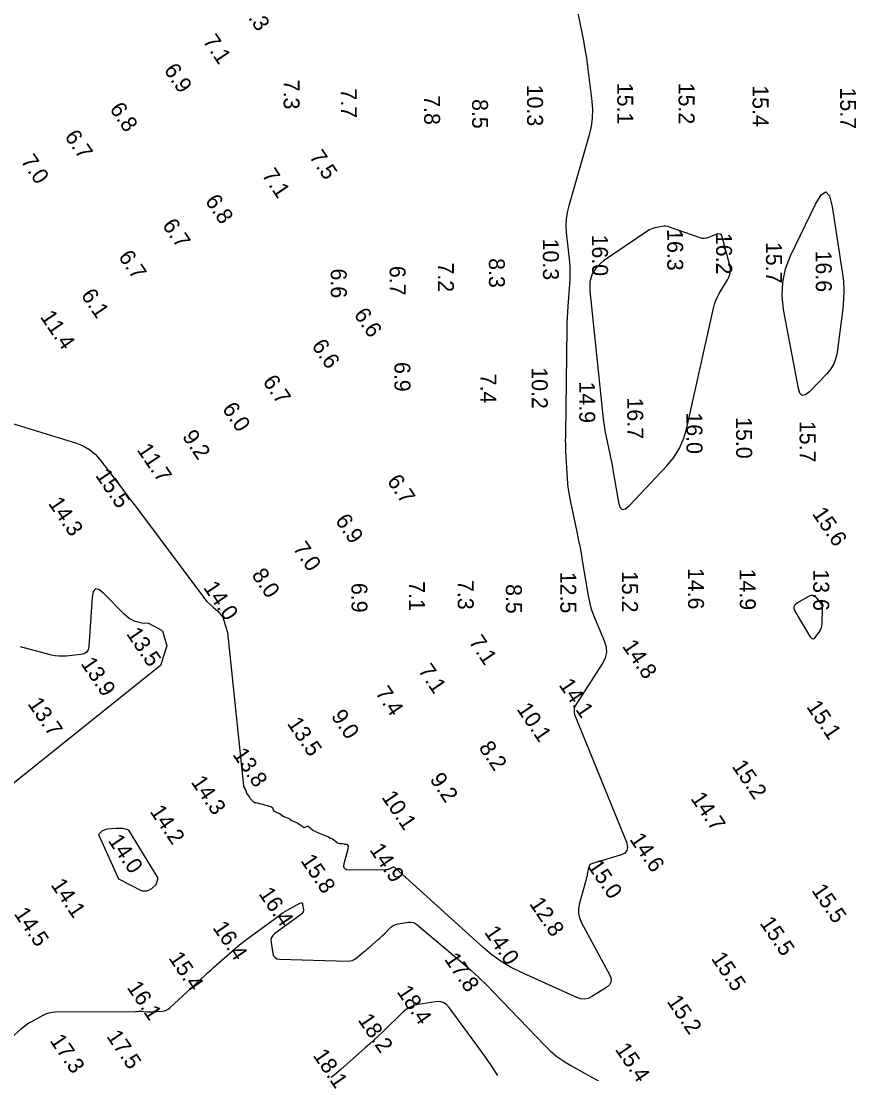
# Model space of a CAD drawing. Extents: x 824616 to 827440, y 158441 to 163197.
# Drawn here: x 826348.7 to 826608.3, y 160568.9 to 160898.9 of the extents above; entities that cross this region are included whole.
import ezdxf

# ---------------------------------------------------------------- set-up
doc = ezdxf.new("R2010")
doc.units = 0
for name, color, linetype in [('V-CHAN-CONT-EL14', 7, 'Continuous'), ('V-CHAN-CONT-EL16', 7, 'Continuous'), ('V-CHAN-CONT-EL18', 7, 'Continuous'), ('V-TOPO-SOUN', 7, 'Continuous')]:
    doc.layers.add(name, color=color, linetype=linetype)

msp = doc.modelspace()

# ---------------------------------------------------------------- linework, layer by layer
at = {"layer": 'V-CHAN-CONT-EL14'}
for points in [[(826521.03, 160912.14), (826524.52, 160895.34), (826525.05, 160892.67), (826525.52, 160889.99), (826525.94, 160887.3), (826526.31, 160884.61), (826527.66, 160873.81), (826527.86, 160871.12), (826527.79, 160868.45), (826527.44, 160865.8), (826526.82, 160863.18), (826520.41, 160840.94), (826519.92, 160838.88), (826519.63, 160836.81), (826519.54, 160834.72), (826519.66, 160832.61), (826520.61, 160823.39), (826520.75, 160821.65), (826520.81, 160819.92), (826520.79, 160818.18), (826520.69, 160816.44), (826520.14, 160809.49), (826520.01, 160807.75), (826519.92, 160806.01), (826519.85, 160804.27), (826519.82, 160802.53), (826519.53, 160777.56), (826519.52, 160776.43), (826519.5, 160775.29), (826519.48, 160774.16), (826519.46, 160773.02), (826519.36, 160768.48), (826519.35, 160767.35), (826519.36, 160766.21), (826519.39, 160765.08), (826519.44, 160763.95), (826519.92, 160755.61), (826520.05, 160753.84), (826520.25, 160752.09), (826520.52, 160750.34), (826520.86, 160748.61), (826522.96, 160738.75), (826523.42, 160736.52), (826523.86, 160734.3), (826524.27, 160732.06), (826524.66, 160729.83), (826526.53, 160718.69), (826526.9, 160716.83), (826527.38, 160714.99), (826527.97, 160713.19), (826528.66, 160711.42), (826531.65, 160704.4), (826532.17, 160702.66), (826532.25, 160700.96), (826531.88, 160699.3), (826531.07, 160697.68), (826522.43, 160684.28), (826522.32, 160684.08), (826522.24, 160683.88), (826522.19, 160683.67), (826522.17, 160683.45), (826522.14, 160682.21), (826522.14, 160682.15), (826522.15, 160682.09), (826522.15, 160682.04), (826522.16, 160681.98), (826522.21, 160681.76), (826522.23, 160681.71), (826522.24, 160681.65), (826522.26, 160681.6), (826522.28, 160681.55), (826538.52, 160641.48), (826538.87, 160640.05), (826538.66, 160638.9), (826537.89, 160638.01), (826536.55, 160637.4), (826527.82, 160634.85), (826527.37, 160634.66), (826527.02, 160634.38), (826526.78, 160634), (826526.63, 160633.54), (826526.25, 160631.49), (826526.15, 160630.98), (826526.04, 160630.47), (826525.92, 160629.97), (826525.79, 160629.47), (826523.74, 160621.93), (826523.49, 160620.52), (826523.51, 160619.15), (826523.8, 160617.8), (826524.36, 160616.48), (826533.27, 160599.8), (826533.69, 160598.67), (826533.65, 160597.65), (826533.18, 160596.76), (826532.26, 160595.98), (826527.68, 160593.11), (826526.52, 160592.55), (826525.34, 160592.31), (826524.14, 160592.39), (826522.92, 160592.79), (826505.57, 160600.65), (826502.35, 160602.27), (826499.28, 160604.12), (826496.36, 160606.2), (826493.59, 160608.51), (826466.03, 160633.43), (826465.82, 160633.58), (826465.6, 160633.65), (826465.37, 160633.64), (826465.13, 160633.56), (826464.14, 160633.08), (826463.89, 160632.98), (826463.63, 160632.9), (826463.37, 160632.86), (826463.1, 160632.84), (826451.66, 160632.71), (826450.71, 160632.84), (826450.12, 160633.24), (826449.89, 160633.91), (826450.01, 160634.86), (826451.3, 160639.44), (826451.43, 160640.23), (826451.23, 160640.61), (826451.11, 160640.71), (826450.9, 160640.75), (826450.76, 160640.77), (826450.64, 160640.8), (826450.46, 160640.82), (826450.31, 160640.83), (826450.14, 160640.84), (826449.88, 160640.85), (826449.36, 160640.95), (826449.11, 160640.96), (826448.76, 160641.01), (826448.49, 160641.08), (826447.97, 160641.24), (826447.75, 160641.43), (826446.38, 160642.44), (826446.12, 160642.54), (826445.7, 160642.69), (826444.86, 160643.21), (826443.64, 160643.71), (826442.86, 160644.02), (826440.25, 160645.18), (826438.69, 160646.51), (826437.53, 160646.04), (826435.55, 160647.41), (826435.35, 160647.44), (826433.23, 160648.45), (826433.13, 160648.68), (826430.96, 160649.61), (826429.62, 160650.46), (826429, 160650.75), (826428.59, 160650.91), (826428.43, 160650.99), (826428.11, 160651.22), (826427.88, 160651.55), (826427.65, 160652.15), (826427.02, 160652.64), (826425.97, 160652.86), (826422.49, 160653.82), (826421.94, 160653.89), (826421.18, 160654.57), (826420.65, 160655.06), (826420.31, 160655.76), (826419.56, 160656.85), (826419.05, 160658.15), (826418.47, 160659.22)], [(826345.7, 160772.89), (826366.09, 160766.58), (826368.24, 160765.73), (826370.19, 160764.59), (826371.93, 160763.15), (826373.47, 160761.42), (826379.2, 160753.91), (826380.63, 160752.03), (826382.06, 160750.15), (826383.48, 160748.26), (826384.9, 160746.37), (826406.89, 160717.02), (826408.96, 160715.13), (826410.51, 160713.83), (826411.95, 160712.07), (826413.43, 160707.22), (826418.47, 160659.22)], [(826393.08, 160707.77), (826388.77, 160710.09), (826386.57, 160710.15), (826384.53, 160710.66), (826382.67, 160711.63), (826380.98, 160713.04), (826374.55, 160719.61), (826373.13, 160720.76), (826372.06, 160720.92), (826371.36, 160720.11), (826371.03, 160718.31), (826369.97, 160702.87), (826369.76, 160701.84), (826369.28, 160701.07), (826368.52, 160700.56), (826367.51, 160700.31), (826362.89, 160699.83), (826361.74, 160699.77), (826360.6, 160699.8), (826359.47, 160699.94), (826358.34, 160700.18), (826348.54, 160702.77)], [(826393.08, 160707.77), (826394.48, 160703.04), (826392.42, 160696.85), (826339.2, 160654.22)], [(826391.68, 160630.25), (826382.52, 160645.24), (826380.71, 160645.8), (826378.6, 160645.76), (826375.62, 160645.6), (826374.12, 160645.02), (826373.01, 160643.91), (826379.24, 160630.04), (826386.58, 160626.26), (826388.26, 160626.22), (826389.71, 160627.01), (826391.13, 160628.24), (826391.68, 160630.25)]]:
    msp.add_lwpolyline(points, dxfattribs=at)
msp.add_lwpolyline([(826596.84, 160718.98), (826597.26, 160718.82), (826597.65, 160718.48), (826599.16, 160716.74), (826599.48, 160716.29), (826599.71, 160715.8), (826599.84, 160715.28), (826599.88, 160714.73), (826599.73, 160709.91), (826599.67, 160709.31), (826599.53, 160708.74), (826599.31, 160708.19), (826599, 160707.68), (826597.6, 160705.67), (826597.25, 160705.29), (826596.92, 160705.18), (826596.59, 160705.32), (826596.27, 160705.71), (826591.38, 160713.91), (826591.06, 160714.68), (826591.06, 160715.36), (826591.39, 160715.96), (826592.03, 160716.48), (826595.91, 160718.76), (826596.39, 160718.96)], close=True, dxfattribs=at)
at = {"layer": 'V-CHAN-CONT-EL16'}
for points in [[(826600.99, 160845.32), (826602.14, 160844.08), (826602.97, 160840.75), (826606.16, 160820.28), (826606.51, 160817.37), (826606.65, 160814.47), (826606.59, 160811.56), (826606.31, 160808.65), (826604.56, 160795.08), (826604.17, 160793.19), (826603.5, 160791.44), (826602.56, 160789.83), (826601.33, 160788.34), (826595.87, 160782.68), (826594.63, 160781.68), (826593.64, 160781.52), (826592.9, 160782.2), (826592.41, 160783.72), (826587.76, 160808.44), (826587.28, 160812.79), (826587.49, 160817.05), (826588.39, 160821.22), (826589.98, 160825.3), (826597.77, 160841.52), (826599.54, 160844.46)], [(826562.92, 160830.7), (826562.26, 160830.75), (826561.6, 160830.92), (826552.05, 160834.3), (826551.48, 160834.47), (826550.91, 160834.55), (826550.33, 160834.56), (826549.74, 160834.48), (826547.38, 160834.04), (826546.8, 160833.9), (826546.24, 160833.7), (826545.71, 160833.45), (826545.2, 160833.14), (826531.33, 160823.68), (826529.2, 160821.83), (826527.77, 160819.65), (826527.04, 160817.16), (826527, 160814.33), (826531.26, 160774.19), (826531.43, 160772.79), (826531.63, 160771.39), (826531.87, 160770), (826532.15, 160768.61), (826533.33, 160763.09), (826533.61, 160761.7), (826533.89, 160760.32), (826534.14, 160758.93), (826534.39, 160757.54), (826535.97, 160748.12), (826536.45, 160746.52), (826537.19, 160745.82), (826538.2, 160745.99), (826539.48, 160747.05), (826551.13, 160759.42), (826553.34, 160762.1), (826555.13, 160764.99), (826556.51, 160768.1), (826557.48, 160771.42), (826565.78, 160808.94), (826566.1, 160810.14), (826566.51, 160811.3), (826567.02, 160812.42), (826567.62, 160813.51), (826570.23, 160817.77), (826570.76, 160818.85), (826571.04, 160819.97), (826571.08, 160821.12), (826570.88, 160822.31), (826568.5, 160831.24), (826568.26, 160831.8), (826567.91, 160832.13), (826567.43, 160832.21), (826566.84, 160832.06), (826564.23, 160830.99), (826563.58, 160830.78)]]:
    msp.add_lwpolyline(points, close=True, dxfattribs=at)
msp.add_lwpolyline([(826345.52, 160580.13), (826348.77, 160583.02), (826349.55, 160583.68), (826350.36, 160584.28), (826351.2, 160584.84), (826352.08, 160585.36), (826355.65, 160587.32), (826356.56, 160587.74), (826357.5, 160588.05), (826358.48, 160588.24), (826359.48, 160588.31), (826384.67, 160588.43), (826384.8, 160588.43), (826384.93, 160588.44), (826385.07, 160588.46), (826385.2, 160588.48), (826385.72, 160588.58), (826385.85, 160588.6), (826385.98, 160588.61), (826386.11, 160588.61), (826386.24, 160588.59), (826388.24, 160588.35), (826388.61, 160588.32), (826388.99, 160588.3), (826389.37, 160588.3), (826389.75, 160588.32), (826393.01, 160588.58), (826393.66, 160588.68), (826394.26, 160588.89), (826394.82, 160589.19), (826395.34, 160589.6), (826406.48, 160599.85), (826407.34, 160600.64), (826408.2, 160601.42), (826409.07, 160602.2), (826409.94, 160602.98), (826414.87, 160607.34), (826415.99, 160608.31), (826417.14, 160609.25), (826418.3, 160610.17), (826419.49, 160611.07), (826429.52, 160618.46), (826430.21, 160618.96), (826430.93, 160619.43), (826431.65, 160619.88), (826432.39, 160620.3), (826436.17, 160622.39), (826436.5, 160622.51), (826436.74, 160622.49), (826436.92, 160622.31), (826437.02, 160621.98), (826437.27, 160620.36), (826437.28, 160619.98), (826437.2, 160619.64), (826437.02, 160619.33), (826436.74, 160619.07), (826428.22, 160612.79), (826427.62, 160612.23), (826427.24, 160611.59), (826427.07, 160610.86), (826427.11, 160610.05), (826427.7, 160606.62), (826427.93, 160605.87), (826428.35, 160605.32), (826428.95, 160604.99), (826429.72, 160604.86), (826451.22, 160604.25), (826451.89, 160604.29), (826452.52, 160604.44), (826453.12, 160604.7), (826453.67, 160605.08), (826455.82, 160606.81), (826456.35, 160607.25), (826456.88, 160607.69), (826457.41, 160608.14), (826457.93, 160608.59), (826460.65, 160610.98), (826461.16, 160611.43), (826461.66, 160611.89), (826462.16, 160612.35), (826462.65, 160612.82), (826464.6, 160614.72), (826465.11, 160615.14), (826465.66, 160615.48), (826466.27, 160615.73), (826466.92, 160615.88), (826470.22, 160616.4), (826470.97, 160616.44), (826471.68, 160616.33), (826472.34, 160616.06), (826472.96, 160615.63), (826487.18, 160603.62), (826489.71, 160601.42), (826492.19, 160599.15), (826494.61, 160596.82), (826496.96, 160594.43), (826512.82, 160577.88), (826514.71, 160576.05), (826516.72, 160574.37), (826518.86, 160572.85), (826521.11, 160571.49), (826532.72, 160565.08)], dxfattribs=at)
at = {"layer": 'V-CHAN-CONT-EL18'}
msp.add_lwpolyline([(826498.18, 160568.41), (826496.41, 160571.09), (826494.6, 160573.74), (826492.73, 160576.36), (826482.99, 160589.72), (826482.11, 160590.66), (826481.1, 160591.28), (826479.94, 160591.56), (826478.65, 160591.51), (826473.21, 160590.65), (826471.89, 160590.34), (826470.67, 160589.85), (826469.55, 160589.17), (826468.51, 160588.3), (826462.25, 160582.21), (826460.87, 160580.88), (826459.47, 160579.57), (826458.06, 160578.28), (826456.63, 160577.01), (826448.95, 160570.28), (826447.48, 160569.01), (826446, 160567.75)], dxfattribs=at)

# ---------------------------------------------------------------- texts
at = {"layer": 'V-TOPO-SOUN'}
for s, rotation, p in [('7.3', 304.2, (826417.72, 160902.97)), ('7.1', 304.2, (826405.59, 160892.63)), ('6.9', 304.2, (826393.34, 160883.54)), ('7.3', 270.2, (826431.04, 160880.49)), ('7.7', 270.2, (826448.97, 160877.77)), ('10.3 ', 270.2, (826507.34, 160878.92)), ('15.1 ', 270.2, (826535.61, 160879.52)), ('15.2 ', 270.2, (826554.84, 160879.54)), ('15.4 ', 270.2, (826578.04, 160878.74)), ('15.7 ', 270.2, (826605.49, 160878.04)), ('7.8', 270.2, (826475.08, 160875.62)), ('8.5', 270.2, (826490.13, 160874.42)), ('6.8', 304.2, (826376.33, 160871.33)), ('6.7', 304.2, (826362.22, 160862.7)), ('7.0', 304.2, (826348.5, 160855.01)), ('7.5', 304.2, (826438.91, 160856.37)), ('7.1', 304.2, (826424.07, 160850.61)), ('6.8', 304.2, (826406.27, 160842.49)), ('6.7', 304.2, (826392.84, 160834.87)), ('16.0 ', 270.2, (826527.7, 160831.96)), ('16.3 ', 270.2, (826551.27, 160833.65)), ('16.2 ', 270.2, (826566.59, 160832.5)), ('10.3 ', 270.2, (826512.3, 160830.67)), ('15.7 ', 270.2, (826582.23, 160829.64)), ('6.7', 304.2, (826379.08, 160825)), ('8.3', 270.2, (826495.38, 160824.55)), ('16.6 ', 270.2, (826597.84, 160826.93)), ('6.6', 270.2, (826445.82, 160821.31)), ('6.7', 270.2, (826464.28, 160822.13)), ('7.2', 270.2, (826479.41, 160823.2)), ('6.1', 304.2, (826367.36, 160812.93)), ('11.4 ', 304.2, (826354.58, 160806.17)), ('6.6', 304.2, (826452.87, 160806.92)), ('6.6', 304.2, (826439.66, 160797.12)), ('6.9', 270.2, (826465.77, 160792)), ('6.7', 304.2, (826424.32, 160785.89)), ('7.4', 270.2, (826492.71, 160788.35)), ('10.2 ', 270.2, (826508.8, 160790.34)), ('14.9 ', 270.2, (826523.69, 160785.9)), ('6.0', 304.2, (826411.62, 160777.34)), ('16.7 ', 270.2, (826538.75, 160780.89)), ('16.0 ', 270.2, (826557.29, 160776.21)), ('15.0 ', 270.2, (826572.87, 160774.73)), ('15.7 ', 270.2, (826592.78, 160773.56)), ('9.2', 304.2, (826399.08, 160768.65)), ('11.7 ', 304.2, (826384.9, 160764.47)), ('15.5 ', 304.2, (826371.86, 160756.48)), ('6.7', 304.2, (826463.3, 160754.69)), ('14.3 ', 304.2, (826357.1, 160747.69)), ('15.6 ', 304.2, (826596.54, 160744.49)), ('6.9', 304.2, (826447.05, 160742.33)), ('7.0', 304.2, (826433.79, 160733.62)), ('8.0', 304.2, (826420.85, 160725.27)), ('12.5 ', 270.2, (826517.75, 160726.25)), ('15.2 ', 270.2, (826537.09, 160726.5)), ('14.6 ', 270.2, (826557.78, 160727.48)), ('14.9 ', 270.2, (826574, 160727.24)), ('13.6 ', 270.2, (826597.04, 160727.03)), ('14.0 ', 304.2, (826405.73, 160721.3)), ('6.9', 270.2, (826452.29, 160722.76)), ('7.1', 270.2, (826470.32, 160723.3)), ('7.3', 270.2, (826485.6, 160723.68)), ('8.5', 270.2, (826500.72, 160722.4)), ('13.5 ', 304.2, (826381.57, 160706.83)), ('7.1', 304.2, (826488.93, 160704.32)), ('14.8 ', 304.2, (826537.01, 160702.95)), ('13.9 ', 304.2, (826367.3, 160697.48)), ('7.1', 304.2, (826473.06, 160695.31)), ('14.1 ', 304.2, (826517.16, 160690.8)), ('7.4', 304.2, (826459.61, 160688.3)), ('13.7 ', 304.2, (826350.67, 160684.87)), ('15.1 ', 304.2, (826594.76, 160683.96)), ('9.0', 304.2, (826445.76, 160681.01)), ('10.1 ', 304.2, (826503.95, 160683.21)), ('13.5 ', 304.2, (826431.96, 160678.7)), ('8.2', 304.2, (826492.03, 160671.13)), ('13.8 ', 304.2, (826414.9, 160669)), ('15.2 ', 304.2, (826571.4, 160665.28)), ('14.3 ', 304.2, (826401.86, 160660.36)), ('9.2', 304.2, (826476.69, 160661.2)), ('10.1 ', 304.2, (826461.61, 160655.61)), ('14.7 ', 304.2, (826558.47, 160655.2)), ('14.2 ', 304.2, (826388.96, 160651.13)), ('14.0 ', 304.2, (826375.84, 160641.98)), ('14.6 ', 304.2, (826539.34, 160642.4)), ('14.9 ', 304.2, (826457.81, 160639.14)), ('15.8 ', 304.2, (826436.21, 160635.72)), ('15.0 ', 304.2, (826526.12, 160634.02)), ('14.1 ', 304.2, (826357.91, 160628.12)), ('16.4 ', 304.2, (826423.05, 160625.36)), ('15.5 ', 304.2, (826596.38, 160626.41)), ('12.8 ', 304.2, (826507.91, 160622.21)), ('14.5 ', 304.2, (826346.37, 160619.07)), ('16.4 ', 304.2, (826408.63, 160614.73)), ('15.5 ', 304.2, (826580.13, 160616.15)), ('14.0 ', 304.2, (826493.79, 160613.29)), ('15.4 ', 304.2, (826394.84, 160605.18)), ('17.8 ', 304.2, (826481.26, 160604.83)), ('15.5 ', 304.2, (826564.88, 160605.08)), ('16.1 ', 304.2, (826381.76, 160595.98)), ('18.4 ', 304.2, (826466.39, 160594.61)), ('15.2 ', 304.2, (826551.02, 160591.58)), ('18.2 ', 304.2, (826454.19, 160585.78)), ('17.3 ', 304.2, (826357.59, 160579.32)), ('17.5 ', 304.2, (826375.37, 160580.63)), ('18.1 ', 304.2, (826440.07, 160574.68)), ('15.4 ', 304.2, (826534.79, 160576.58))]:
    msp.add_text(s, height=5, rotation=rotation, dxfattribs=at).set_placement(p)

doc.saveas('drawing.dxf')
